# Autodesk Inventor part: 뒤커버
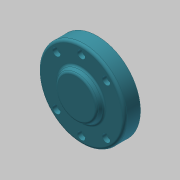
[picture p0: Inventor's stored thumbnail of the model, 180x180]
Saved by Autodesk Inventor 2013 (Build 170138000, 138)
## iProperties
Company: 한국ATC센터
Created: 2015-12
Part Number: 뒤커버
Document SubType Name: Modeling
Designer: mdu
Density: 2.71 g/cm^3
Mass: 105.756 g
Surface Area: 115.002 cm^2
Volume: 39.0244 cm^3
Material: 알루미늄 6061
Author: mdu
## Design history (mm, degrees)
sketch "스케치1"
  geometry: L1 (-10.5, 0)-(10.5, 0); L2 (10.5, 0)-(10.5, 22.5); L3 (10.5, 22.5)-(5.5, 22.5); L4 (5.5, 22.5)-(5.5, 32.5); L5 (5.5, 32.5)-(-6.5, 32.5); L6 (-6.5, 32.5)-(-6.5, 17.5); L7 (-6.5, 17.5)-(-10.5, 15.191); L8 (-10.5, 15.191)-(-10.5, 0); 2 further points
  constraints: 16 end point, 3 parallel, 3 perpendicular, 1 coincident, 1 horizontal, 1 midpoint
  dimensions: "d0" = 21 distance of L1.start L1.end; "d1" = 65 diameter of L5 L1; "d2" = 45 diameter of L3 L1; "d3" = 35 diameter of L6.end L1; "d4" = 120 deg angle of L7 L6; "d5" = 12 distance of L4.end L5.end; "d6" = 5 distance of L2.end L3.end
revolve "회전1" sketch "스케치1" stored, may be unused: angle "d7" = 90 deg
sketch "스케치2"
  geometry: L1 (0, 0)-(32.5, 0); L2 (0, 0)-(0, 26.5); 1 further point
  constraints: 4 end point, 1 horizontal, 1 horizontal alignment, 1 other
  dimensions: "d8" = 90 deg angle of L1 L2; "d9" = 26.5 distance of L1.start L2.end
hole "구멍1" sketch "스케치2" at (0, 26.5) diameter "d10" = 3.4; stored, may be unused: countersink angle "d14" = 90 deg, drill point angle "d16" = 118 deg; dims "d11" = 6, "d12" = 6, "d13" = 3.3, "d15" = 8
fillet "모깎기1" dims "d20" = 2
hole "구멍2" diameter "d23" = 15; stored, may be unused: countersink angle "d27" = 90 deg, drill point angle "d29" = 0 deg; dims "d21" = 10, "d22" = 10, "d24" = 6, "d25" = 35, "d26" = 11, "d28" = 14
chamfer "모따기1" distance "d39" = 1; stored, may be unused: second distance "d40" = 2, angle "d41" = 45 deg
fillet "모깎기2" dims "d42" = 0.3
chamfer "모따기3" distance "d57" = 1; stored, may be unused: second distance "d58" = 2, angle "d59" = 45 deg
fillet "모깎기4" dims "d60" = 1
node "솔리드1"
pattern_circular "원형 패턴1" dims angle "d18" = 360 deg
